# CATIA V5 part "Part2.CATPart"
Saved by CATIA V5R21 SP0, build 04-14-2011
Part number: Part2
Bounding box of the stored display mesh (mm): x -29.961 to 100, y -30 to 30, z -29.961 to 29.961
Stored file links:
  D:\CATIA V5R21 E-RESOURCES\CATIA-V5R21\catia-v5r21-prt\c16-catia-v5r20-prt\Sperical Joint-(Fig16-27)\CAT_V5R21_Part2.CATPart
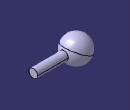
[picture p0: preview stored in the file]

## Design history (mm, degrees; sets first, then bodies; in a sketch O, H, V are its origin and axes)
Body1 (main body)
  Sketch1 on xy-plane, origin (0, 0, 0), H (1, 0, 0), V (0, 1, 0)
    arc A1 centre (0, 0) radius 30 from (0, -30) to (0, 30) ccw
    point P1 (0, 30)
    point P2 (0, -30)
    line L1 (0, -30) -> (0, 30)
    length L1 = 60
    coincidence: P1 V, P2 V
    vertical: L1 V
  Shaft1: profile Sketch1, axis Sketch1.L1, angle 360
  Sketch2 on yz-plane, origin (0, 0, 0), H (0, 1, 0), V (0, 0, 1)
    circle A1 centre (0, 0) radius 10
    radius A1 = 10
  Pad1: profile Sketch2, direction (1, 0, 0), length 100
